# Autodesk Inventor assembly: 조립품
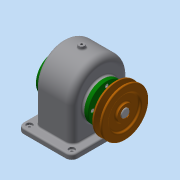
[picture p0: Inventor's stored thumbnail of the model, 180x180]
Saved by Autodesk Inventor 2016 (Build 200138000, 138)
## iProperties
Created: 2018-11
Part Number: 조립품
Material: 일반
Document SubType Name: Assembly
Designer: user
Author: user
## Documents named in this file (14)
- C:\Users\user\Desktop\481111V1013\조립품.iam
- C:\Users\user\Desktop\481111V1013\V-벨트풀리.ipt
- C:\Users\user\Desktop\481111V1013\뒤커버.ipt
- C:\Users\user\Desktop\481111V1013\멈춤나사 M4.ipt
- C:\Users\user\Desktop\481111V1013\베어링 6203.ipt
- C:\Users\user\Desktop\481111V1013\본체.ipt
- C:\Users\user\Desktop\481111V1013\볼트 M4.ipt
- C:\Users\user\Desktop\481111V1013\부시.ipt
- C:\Users\user\Desktop\481111V1013\스퍼기어.ipt
- C:\Users\user\Desktop\481111V1013\앞커버.ipt
- C:\Users\user\Desktop\481111V1013\오일 실 28 40 8.ipt
- C:\Users\user\Desktop\481111V1013\축.ipt
- C:\Users\user\Desktop\481111V1013\키 5x5x18.ipt
- C:\Users\user\Desktop\481111V1013\키 6x6x22.ipt
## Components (1 placed, 1 different names)
1. V-벨트풀리:1
